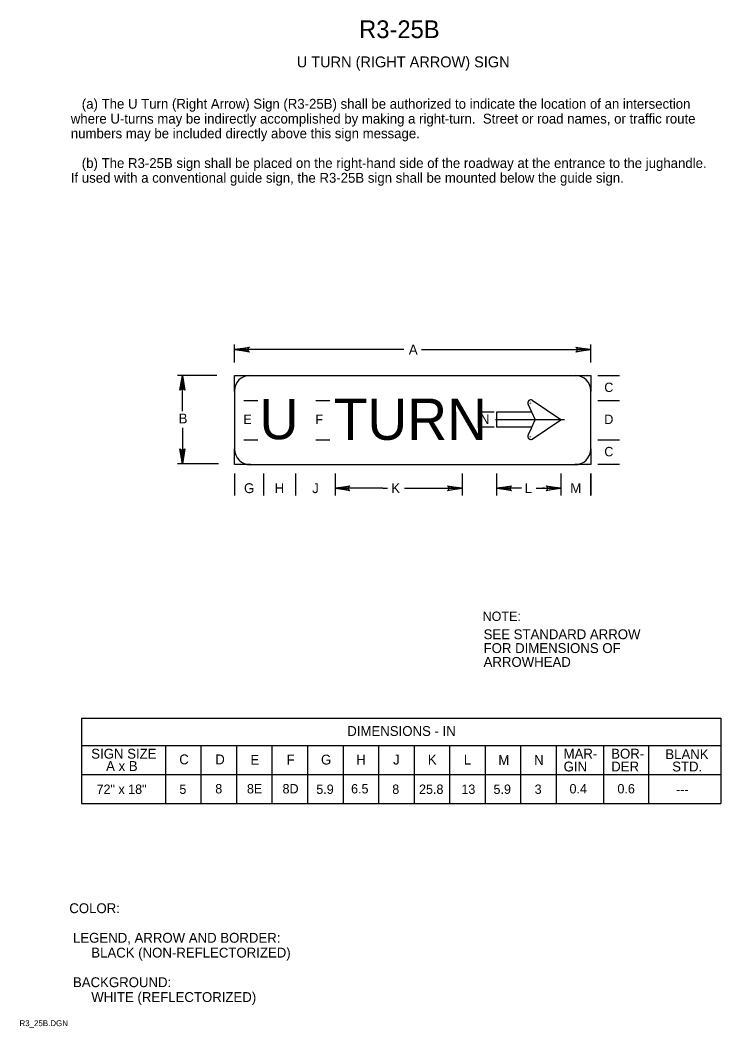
# Model space of a CAD drawing. Extents: x 0.5 to 7.5, y 0.2 to 10.2.
import ezdxf

# ---------------------------------------------------------------- set-up
doc = ezdxf.new("R2010")
doc.units = 0
for name, color, linetype in [('1', 7, 'Continuous'), ('11', 7, 'Continuous'), ('12', 7, 'Continuous'), ('2', 7, 'Continuous'), ('3', 7, 'Continuous')]:
    doc.layers.add(name, color=color, linetype=linetype)

# ---------------------------------------------------------------- blocks, each defined once
blk = doc.blocks.new('RARROW')
at = {"layer": '3'}
for p, q in [((-84.9, 11.2), (-89.2, 15.1)), ((-89.2, 15.1), (0, 0)), ((0, 0), (-89.2, -14.9)), ((-84.9, 11.2), (-81.7, 4.8)), ((0, 0), (-84.9, 11.2)), ((-84.6, -10.6), (0, 0)), ((-81.7, 4.8), (0, 0)), ((0, 0), (-81.7, -4.3)), ((-89.2, -14.9), (-84.6, -10.6)), ((-81.7, -4.3), (-84.6, -10.6))]:
    blk.add_line(p, q, dxfattribs=at)

msp = doc.modelspace()

# ---------------------------------------------------------------- linework, layer by layer
at = {"layer": '11'}
for p, q in [((2.638, 6.502), (2.638, 6.66)), ((2.638, 6.66), (2.796, 6.66)), ((6.032, 6.66), (6.19, 6.66)), ((6.19, 6.66), (6.19, 6.502)), ((2.638, 5.772), (2.638, 5.929)), ((6.19, 5.929), (6.19, 5.772)), ((2.796, 5.772), (2.638, 5.772)), ((6.19, 5.772), (6.032, 5.772))]:
    msp.add_line(p, q, dxfattribs=at)
at = {"layer": '12'}
for p, q in [((5.566, 6.373), (5.599, 6.298)), ((5.892, 6.219), (5.607, 6.413)), ((5.599, 6.14), (5.567, 6.068)), ((5.606, 6.025), (5.892, 6.219))]:
    msp.add_line(p, q, dxfattribs=at)
for centre, major_axis, start_param, end_param in [((5.592, 6.386), (0, 0.032), 5.722676, 8.270867), ((5.592, 6.053), (0, 0.0318), 1.068412, 3.650841)]:
    msp.add_ellipse(centre, major_axis=major_axis, ratio=0.881834, start_param=start_param, end_param=end_param, dxfattribs=at)
at = {"layer": '3'}
for p, q in [((2.638, 6.792), (2.638, 6.969)), ((6.19, 6.792), (6.19, 6.969)), ((4.327, 6.919), (2.638, 6.919)), ((4.501, 6.919), (6.19, 6.919)), ((2.462, 6.662), (2.068, 6.662)), ((2.117, 6.304), (2.117, 6.662)), ((2.786, 6.66), (6.042, 6.66)), ((6.26, 6.66), (6.477, 6.66)), ((2.638, 6.512), (2.638, 5.929)), ((6.19, 5.929), (6.19, 6.512)), ((2.73, 6.413), (2.869, 6.413)), ((3.449, 6.413), (3.588, 6.413)), ((6.26, 6.413), (6.477, 6.413)), ((5.228, 6.294), (5.097, 6.294)), ((5.601, 6.294), (5.252, 6.294)), ((5.252, 6.294), (5.252, 6.147)), ((5.599, 6.298), (5.636, 6.219)), ((2.117, 6.14), (2.117, 5.781)), ((5.228, 6.147), (5.098, 6.147)), ((5.24, 6.221), (5.929, 6.221)), ((5.602, 6.147), (5.252, 6.147)), ((5.599, 6.14), (5.636, 6.219)), ((2.73, 6.018), (2.869, 6.018)), ((3.449, 6.018), (3.588, 6.018)), ((6.26, 6.018), (6.477, 6.018)), ((2.477, 5.781), (2.068, 5.781)), ((2.796, 5.772), (6.032, 5.772)), ((6.477, 5.772), (6.26, 5.772)), ((2.638, 5.682), (2.638, 5.465)), ((2.927, 5.682), (2.927, 5.465)), ((3.246, 5.682), (3.246, 5.465)), ((3.64, 5.682), (3.64, 5.465)), ((4.907, 5.682), (4.907, 5.465)), ((5.252, 5.682), (5.252, 5.465)), ((5.892, 5.682), (5.892, 5.465)), ((6.19, 5.682), (6.19, 5.465)), ((6.19, 5.465), (6.19, 5.682)), ((4.116, 5.536), (3.64, 5.536)), ((4.116, 5.536), (4.163, 5.536)), ((4.332, 5.536), (4.907, 5.536)), ((5.499, 5.536), (5.254, 5.536)), ((5.646, 5.536), (5.891, 5.536)), ((5.73, 5.536), (5.708, 5.536)), ((1.11, 3.243), (1.11, 2.392)), ((1.11, 3.243), (7.489, 3.243)), ((7.489, 3.243), (7.489, 2.392)), ((1.11, 2.972), (7.489, 2.972)), ((1.948, 2.972), (1.948, 2.392)), ((2.302, 2.972), (2.302, 2.392)), ((2.657, 2.972), (2.657, 2.392)), ((3.011, 2.972), (3.011, 2.392)), ((3.365, 2.972), (3.365, 2.392)), ((3.72, 2.972), (3.72, 2.392)), ((4.074, 2.972), (4.074, 2.392)), ((4.428, 2.972), (4.428, 2.392)), ((4.783, 2.972), (4.783, 2.392)), ((5.137, 2.972), (5.137, 2.392)), ((5.491, 2.972), (5.491, 2.392)), ((5.846, 2.972), (5.846, 2.392)), ((6.319, 2.972), (6.319, 2.392)), ((6.768, 2.972), (6.768, 2.392)), ((1.11, 2.682), (7.489, 2.682)), ((1.11, 2.392), (7.489, 2.392))]:
    msp.add_line(p, q, dxfattribs=at)
for centre, radius, start, end in [((2.786, 6.512), 0.148, 90, 180), ((6.042, 6.512), 0.148, 0, 90), ((2.796, 5.929), 0.158, 180, 270), ((6.032, 5.929), 0.158, 270, 0)]:
    msp.add_arc(centre, radius, start, end, dxfattribs=at)

# ---------------------------------------------------------------- block references
at = {"layer": '3', "xscale": 0.0016545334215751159, "yscale": 0.0016366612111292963}
for p, rotation in [((2.638, 6.919), 180), ((2.117, 6.662), 90), ((2.117, 5.781), -90), ((3.64, 5.536), 180), ((5.254, 5.536), 180)]:
    msp.add_blockref('RARROW', p, dxfattribs=dict(at, rotation=rotation))
for p in [(6.19, 6.919), (4.908, 5.536), (5.892, 5.536)]:
    msp.add_blockref('RARROW', p, dxfattribs=at)

# ---------------------------------------------------------------- texts
at = {"layer": '1'}
for s, height, p in [('R3-25B', 0.1772, (3.88, 10.025)), ('U TURN (RIGHT ARROW) SIGN', 0.10828, (3.258, 9.734)), ('NOTE:', 0.0935, (5.112, 4.213)), ('SEE STANDARD ARROW', 0.09842, (5.122, 4.031)), ('FOR DIMENSIONS OF', 0.09842, (5.122, 3.893)), ('ARROWHEAD', 0.0984, (5.122, 3.755)), ('COLOR:', 0.0984, (0.989, 1.299)), (' LEGEND, ARROW AND BORDER:', 0.09842, (0.989, 1.004)), ('      BLACK (NON-REFLECTORIZED)', 0.09842, (0.989, 0.856)), (' BACKGROUND:', 0.09842, (0.989, 0.561)), ('      WHITE (REFLECTORIZED)', 0.09842, (0.989, 0.413)), ('R3_25B.DGN', 0.0591, (0.492, 0.172))]:
    msp.add_text(s, height=height, dxfattribs=at).set_placement(p)
at = {"layer": '12'}
for s, height, p in [('U', 0.403, (2.887, 6.025)), ('TURN', 0.4114, (3.627, 6.019))]:
    msp.add_text(s, height=height, dxfattribs=at).set_placement(p)
msp.add_text('+', height=0.0352, rotation=359.8926, dxfattribs=at).set_placement((5.572, 6.369))
at = {"layer": '2'}
for s, height, p in [('   (a) The U Turn (Right Arrow) Sign (R3-25B) shall be authorized to indicate the location of an intersection ', 0.098415, (1.004, 9.321)), ('where U-turns may be indirectly accomplished by making a right-turn.  Street or road names, or traffic route ', 0.098415, (1.004, 9.173)), ('numbers may be included directly above this sign message.', 0.09842, (1.004, 9.026)), ('   (b) The R3-25B sign shall be placed on the right-hand side of the roadway at the entrance to the jughandle.  ', 0.098415, (1.004, 8.73)), ('If used with a conventional guide sign, the R3-25B sign shall be mounted below the guide sign.', 0.09842, (1.004, 8.583))]:
    msp.add_text(s, height=height, dxfattribs=at).set_placement(p)
at = {"layer": '3'}
for s, height, p in [('A', 0.0984, (4.376, 6.87)), ('C', 0.0935, (6.326, 6.496)), ('B', 0.0984, (2.08, 6.183)), ('E', 0.0935, (2.725, 6.177)), ('F', 0.0935, (3.444, 6.177)), ('N', 0.0984, (5.086, 6.176)), ('D', 0.0935, (6.326, 6.177)), ('C', 0.0935, (6.326, 5.855)), ('G', 0.0984, (2.732, 5.488)), ('H', 0.0984, (3.038, 5.488)), ('J', 0.0984, (3.412, 5.488)), ('K', 0.0984, (4.201, 5.488)), ('L', 0.0984, (5.531, 5.488)), ('M', 0.0984, (5.987, 5.488)), ('DIMENSIONS - IN', 0.09842, (3.762, 3.066)), ('SIGN SIZE', 0.0984, (1.208, 2.84)), ('MAR-', 0.0984, (5.92, 2.84)), ('BOR-', 0.0984, (6.395, 2.84)), ('BLANK', 0.0984, (6.935, 2.835)), ('A x B', 0.0984, (1.356, 2.717)), ('C', 0.0984, (2.086, 2.783)), ('D', 0.0984, (2.445, 2.783)), ('E', 0.0984, (2.796, 2.779)), ('F', 0.0984, (3.156, 2.781)), ('G', 0.0984, (3.5, 2.781)), ('H', 0.0984, (3.851, 2.781)), ('J', 0.0984, (4.219, 2.781)), ('K', 0.0984, (4.565, 2.781)), ('L', 0.0984, (4.924, 2.781)), ('M', 0.0984, (5.269, 2.777)), ('N', 0.0984, (5.626, 2.777)), ('GIN', 0.0984, (5.92, 2.712)), ('DER', 0.0984, (6.395, 2.712)), ('STD.', 0.0984, (7.003, 2.712)), ('72" x 18"', 0.0935, (1.261, 2.488)), ('5', 0.0935, (2.087, 2.488)), ('8', 0.0935, (2.445, 2.493)), ('8E', 0.0935, (2.761, 2.493)), ('8D', 0.0935, (3.116, 2.493)), ('5.9', 0.0935, (3.453, 2.488)), ('6.5', 0.0935, (3.8, 2.493)), ('8', 0.0935, (4.211, 2.488)), ('25.8', 0.0935, (4.478, 2.488)), ('13', 0.0935, (4.9, 2.488)), ('5.9', 0.0935, (5.221, 2.488)), ('3', 0.0935, (5.631, 2.488)), ('0.4', 0.0935, (5.979, 2.493)), ('0.6', 0.0935, (6.457, 2.493)), ('---', 0.0935, (7.042, 2.485))]:
    msp.add_text(s, height=height, dxfattribs=at).set_placement(p)
msp.add_text('+', height=0.0352, rotation=0.0163, dxfattribs=at).set_placement((5.572, 6.031))

doc.saveas('drawing.dxf')
